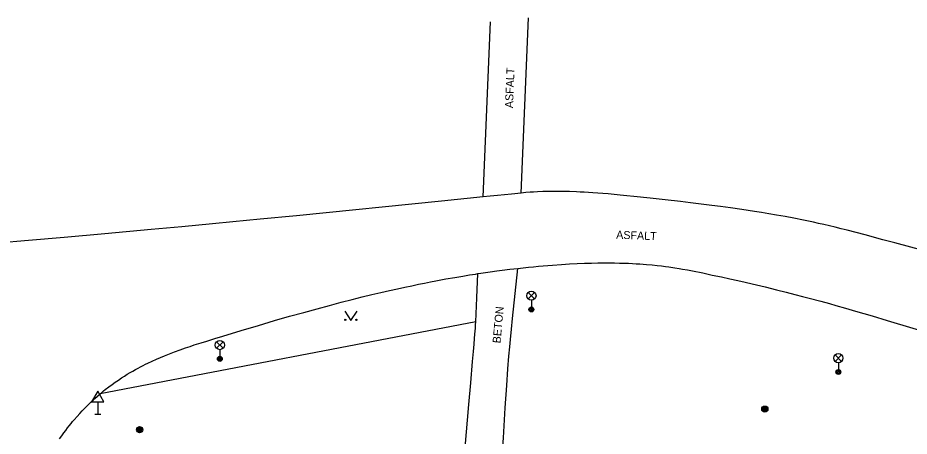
# Model space of a CAD drawing. Extents: x -541281 to -539153, y -1183881 to -1182141.
# Drawn here: x -539853.2 to -539780.8, y -1183203.1 to -1183169.1 of the extents above; entities that cross this region are included whole.
import ezdxf

# ---------------------------------------------------------------- set-up
doc = ezdxf.new("R2010")
doc.units = 0
for name, color, linetype in [('Vrstva 10', 7, 'Continuous'), ('Vrstva 11', 7, 'Continuous'), ('Vrstva 25', 7, 'Continuous'), ('Vrstva 33', 7, 'Continuous'), ('Vrstva 34', 7, 'Continuous'), ('Vrstva 36', 7, 'Continuous'), ('Vrstva 40', 7, 'Continuous')]:
    doc.layers.add(name, color=color, linetype=linetype)

msp = doc.modelspace()

# ---------------------------------------------------------------- linework, layer by layer
at = {"layer": 'Vrstva 10'}
for p, q in [((-539815.43, -1183183.64), (-539818.798, -1183183.975)), ((-539818.798, -1183183.975), (-539830.587, -1183185.158)), ((-539795.35, -1183184.53), (-539796.163, -1183184.42)), ((-539852.324, -1183187.172), (-539857.371, -1183187.609)), ((-539849.441, -1183186.921), (-539852.324, -1183187.172)), ((-539813.254, -1183189.513), (-539812.62, -1183189.44)), ((-539786, -1183192.67), (-539785.21, -1183192.9))]:
    msp.add_line(p, q, dxfattribs=at)
for points in [[(-539808.407, -1183183.203), (-539808.9, -1183183.192), (-539809.331, -1183183.188), (-539809.707, -1183183.189), (-539810.037, -1183183.192), (-539810.325, -1183183.198), (-539810.578, -1183183.206), (-539811.019, -1183183.224), (-539811.349, -1183183.242), (-539811.597, -1183183.258), (-539811.969, -1183183.286), (-539812.34, -1183183.32), (-539813.113, -1183183.398), (-539814.271, -1183183.521), (-539814.85, -1183183.581), (-539815.43, -1183183.64)], [(-539806.516, -1183183.296), (-539806.881, -1183183.273), (-539807.223, -1183183.253), (-539807.544, -1183183.236), (-539807.844, -1183183.223), (-539808.407, -1183183.203)], [(-539805.713, -1183183.357), (-539806.127, -1183183.324), (-539806.516, -1183183.296)], [(-539796.163, -1183184.42), (-539796.876, -1183184.327), (-539797.5, -1183184.248), (-539798.594, -1183184.114), (-539799.415, -1183184.018), (-539800.647, -1183183.877), (-539801.88, -1183183.74), (-539803.186, -1183183.598), (-539803.758, -1183183.538), (-539804.295, -1183183.484), (-539804.798, -1183183.436), (-539805.27, -1183183.394), (-539805.713, -1183183.357)], [(-539785.88, -1183186.34), (-539786.372, -1183186.214), (-539786.849, -1183186.096), (-539787.312, -1183185.986), (-539787.761, -1183185.882), (-539788.196, -1183185.784), (-539788.619, -1183185.692), (-539789.028, -1183185.606), (-539789.426, -1183185.524), (-539790.196, -1183185.372), (-539790.92, -1183185.236), (-539791.6, -1183185.114), (-539792.238, -1183185.005), (-539792.836, -1183184.906), (-539793.398, -1183184.817), (-539793.926, -1183184.736), (-539794.421, -1183184.663), (-539795.35, -1183184.53)], [(-539830.587, -1183185.158), (-539833.534, -1183185.45), (-539835.745, -1183185.665), (-539837.403, -1183185.825), (-539839.891, -1183186.06)], [(-539839.891, -1183186.06), (-539842.38, -1183186.29), (-539846.145, -1183186.629), (-539849.441, -1183186.921)], [(-539782.971, -1183187.108), (-539784.425, -1183186.721), (-539785.88, -1183186.34)], [(-539773.666, -1183189.666), (-539776.712, -1183188.818), (-539778.998, -1183188.187), (-539780.715, -1183187.717), (-539782.004, -1183187.368), (-539782.971, -1183187.108)], [(-539823.033, -1183191.24), (-539822.388, -1183191.095), (-539821.782, -1183190.963), (-539821.214, -1183190.842), (-539820.681, -1183190.732), (-539820.181, -1183190.631), (-539819.712, -1183190.538), (-539819.271, -1183190.453), (-539818.445, -1183190.3), (-539817.721, -1183190.171), (-539817.086, -1183190.064), (-539816.53, -1183189.973), (-539816.043, -1183189.896), (-539815.846, -1183189.866), (-539815.617, -1183189.832), (-539814.87, -1183189.724), (-539814.308, -1183189.647), (-539813.887, -1183189.592), (-539813.254, -1183189.513)], [(-539812.62, -1183189.44), (-539812.18, -1183189.392), (-539811.752, -1183189.347), (-539811.338, -1183189.305), (-539810.935, -1183189.267), (-539810.545, -1183189.232), (-539809.787, -1183189.169), (-539809.076, -1183189.117), (-539808.408, -1183189.076), (-539807.781, -1183189.044), (-539807.193, -1183189.021), (-539806.642, -1183189.005), (-539806.125, -1183188.995), (-539805.64, -1183188.99), (-539805.186, -1183188.991), (-539804.761, -1183188.996)], [(-539804.761, -1183188.996), (-539804.362, -1183189.004), (-539803.989, -1183189.015), (-539803.639, -1183189.028), (-539803.311, -1183189.044), (-539803.004, -1183189.061), (-539802.716, -1183189.079), (-539802.177, -1183189.119), (-539801.707, -1183189.16), (-539801.295, -1183189.202), (-539800.936, -1183189.242), (-539800.623, -1183189.281), (-539800.348, -1183189.317), (-539799.869, -1183189.387), (-539799.511, -1183189.443), (-539799.243, -1183189.489), (-539798.841, -1183189.562), (-539798.44, -1183189.64), (-539797.605, -1183189.812), (-539796.823, -1183189.976), (-539796.091, -1183190.134), (-539795.405, -1183190.284)], [(-539795.405, -1183190.284), (-539794.763, -1183190.428), (-539794.162, -1183190.564), (-539793.599, -1183190.695), (-539792.544, -1183190.945), (-539791.623, -1183191.169), (-539790.818, -1183191.37), (-539790.114, -1183191.549), (-539789.499, -1183191.709), (-539788.962, -1183191.85), (-539788.022, -1183192.103), (-539787.318, -1183192.297), (-539786.79, -1183192.445), (-539786, -1183192.67)], [(-539833.668, -1183194.064), (-539832.361, -1183193.682), (-539831.137, -1183193.331), (-539829.989, -1183193.008), (-539828.913, -1183192.712), (-539827.904, -1183192.442), (-539826.957, -1183192.194), (-539826.069, -1183191.967), (-539825.236, -1183191.76), (-539824.454, -1183191.571)], [(-539824.454, -1183191.571), (-539823.721, -1183191.398), (-539823.033, -1183191.24)], [(-539785.21, -1183192.9), (-539783.839, -1183193.305), (-539782.64, -1183193.661), (-539780.547, -1183194.29), (-539778.979, -1183194.766), (-539777.803, -1183195.126), (-539776.041, -1183195.67)], [(-539842.838, -1183197.23), (-539842.65, -1183197.138), (-539842.284, -1183196.965), (-539841.939, -1183196.81), (-539841.614, -1183196.669), (-539841.307, -1183196.541), (-539841.019, -1183196.425), (-539840.747, -1183196.319), (-539840.491, -1183196.222), (-539840.009, -1183196.045), (-539839.585, -1183195.896), (-539839.212, -1183195.769), (-539838.884, -1183195.66), (-539838.306, -1183195.473), (-539837.87, -1183195.336), (-539837.213, -1183195.132), (-539836.55, -1183194.93), (-539835.062, -1183194.48), (-539833.668, -1183194.064)], [(-539849.806, -1183203.278), (-539849.635, -1183203.033), (-539849.471, -1183202.805), (-539849.314, -1183202.593), (-539849.163, -1183202.396), (-539849.019, -1183202.213), (-539848.882, -1183202.042), (-539848.751, -1183201.883), (-539848.626, -1183201.735), (-539848.388, -1183201.459), (-539848.173, -1183201.221), (-539847.981, -1183201.015), (-539847.81, -1183200.836), (-539847.658, -1183200.681), (-539847.522, -1183200.546), (-539847.281, -1183200.313), (-539847.096, -1183200.139), (-539846.955, -1183200.011), (-539846.739, -1183199.819), (-539846.52, -1183199.63), (-539846.377, -1183199.51), (-539846.236, -1183199.394), (-539846.097, -1183199.283), (-539845.822, -1183199.068), (-539845.553, -1183198.868), (-539845.292, -1183198.68), (-539845.037, -1183198.504), (-539844.789, -1183198.34), (-539844.548, -1183198.185), (-539844.313, -1183198.039), (-539844.084, -1183197.902), (-539843.862, -1183197.774), (-539843.645, -1183197.652), (-539843.435, -1183197.537), (-539843.23, -1183197.429), (-539843.031, -1183197.327), (-539842.838, -1183197.23)]]:
    msp.add_lwpolyline(points, dxfattribs=at)
at = {"layer": 'Vrstva 11'}
for p, q in [((-539812.34, -1183183.32), (-539811.75, -1183169.09)), ((-539815.43, -1183183.64), (-539814.84, -1183169.41)), ((-539815.938, -1183191.818), (-539815.846, -1183189.866)), ((-539816.03, -1183193.77), (-539846.52, -1183199.63)), ((-539813.508, -1183198.951), (-539813.411, -1183197.587))]:
    msp.add_line(p, q, dxfattribs=at)
for points in [[(-539813.411, -1183197.587), (-539813.332, -1183196.564), (-539813.268, -1183195.798), (-539813.218, -1183195.223), (-539813.137, -1183194.361), (-539813.05, -1183193.5), (-539812.835, -1183191.47), (-539812.62, -1183189.44)], [(-539816.043, -1183194.025), (-539816.03, -1183193.77), (-539815.938, -1183191.818)], [(-539816.878, -1183203.973), (-539816.58, -1183200.482), (-539816.434, -1183198.736), (-539816.29, -1183196.99), (-539816.22, -1183196.185), (-539816.164, -1183195.582), (-539816.124, -1183195.129), (-539816.096, -1183194.79), (-539816.059, -1183194.28), (-539816.043, -1183194.025)], [(-539814.14, -1183207.85), (-539814.062, -1183206.953), (-539813.994, -1183206.113), (-539813.934, -1183205.324), (-539813.881, -1183204.585), (-539813.786, -1183203.198), (-539813.629, -1183200.771), (-539813.508, -1183198.951)]]:
    msp.add_lwpolyline(points, dxfattribs=at)
at = {"layer": 'Vrstva 25'}
for centre, radius in [((-539792.56, -1183200.87), 0.25), ((-539792.56, -1183200.87), 0.2), ((-539792.56, -1183200.87), 0.15), ((-539792.56, -1183200.87), 0.1), ((-539792.56, -1183200.87), 0.05), ((-539843.31, -1183202.54), 0.25), ((-539843.31, -1183202.54), 0.2), ((-539843.31, -1183202.54), 0.15), ((-539843.31, -1183202.54), 0.1), ((-539843.31, -1183202.54), 0.05)]:
    msp.add_circle(centre, radius, dxfattribs=at)
at = {"layer": 'Vrstva 33'}
for p, q in [((-539811.775, -1183191.92), (-539811.245, -1183191.39)), ((-539811.775, -1183191.39), (-539811.245, -1183191.92)), ((-539811.51, -1183192.03), (-539811.51, -1183192.78)), ((-539837.065, -1183195.93), (-539836.535, -1183195.4)), ((-539837.065, -1183195.4), (-539836.535, -1183195.93)), ((-539836.8, -1183196.04), (-539836.8, -1183196.79)), ((-539786.855, -1183196.99), (-539786.325, -1183196.46)), ((-539786.855, -1183196.46), (-539786.325, -1183196.99)), ((-539786.59, -1183197.1), (-539786.59, -1183197.85))]:
    msp.add_line(p, q, dxfattribs=at)
for centre, radius in [((-539811.51, -1183191.655), 0.375), ((-539811.51, -1183192.78), 0.2), ((-539811.51, -1183192.78), 0.145), ((-539811.51, -1183192.78), 0.0876), ((-539836.8, -1183195.665), 0.375), ((-539836.8, -1183196.79), 0.2), ((-539836.8, -1183196.79), 0.145), ((-539836.8, -1183196.79), 0.0876), ((-539786.59, -1183196.725), 0.375), ((-539786.59, -1183197.85), 0.2), ((-539786.59, -1183197.85), 0.145), ((-539786.59, -1183197.85), 0.0876)]:
    msp.add_circle(centre, radius, dxfattribs=at)
at = {"layer": 'Vrstva 34'}
for p, q in [((-539846.71, -1183200.272), (-539846.71, -1183201.29)), ((-539846.96, -1183201.29), (-539846.46, -1183201.29))]:
    msp.add_line(p, q, dxfattribs=at)
msp.add_lwpolyline([(-539847.21, -1183200.272), (-539846.21, -1183200.272), (-539846.71, -1183199.406)], close=True, dxfattribs=at)
at = {"layer": 'Vrstva 36'}
msp.add_lwpolyline([(-539826.666, -1183192.914), (-539826.166, -1183193.664), (-539825.666, -1183192.914)], dxfattribs=at)
for centre in [(-539826.616, -1183193.614), (-539825.717, -1183193.614)]:
    msp.add_circle(centre, 0.05, dxfattribs=at)

# ---------------------------------------------------------------- texts
at = {"layer": 'Vrstva 40'}
for s, rotation, p in [('ASFALT', 87.62578, (-539813.01, -1183176.433)), ('ASFALT', 357.6778, (-539804.636, -1183187.02)), ('BETON', 84.83535, (-539814.022, -1183195.544))]:
    msp.add_text(s, height=0.65, rotation=rotation, dxfattribs=at).set_placement(p)

doc.saveas('drawing.dxf')
